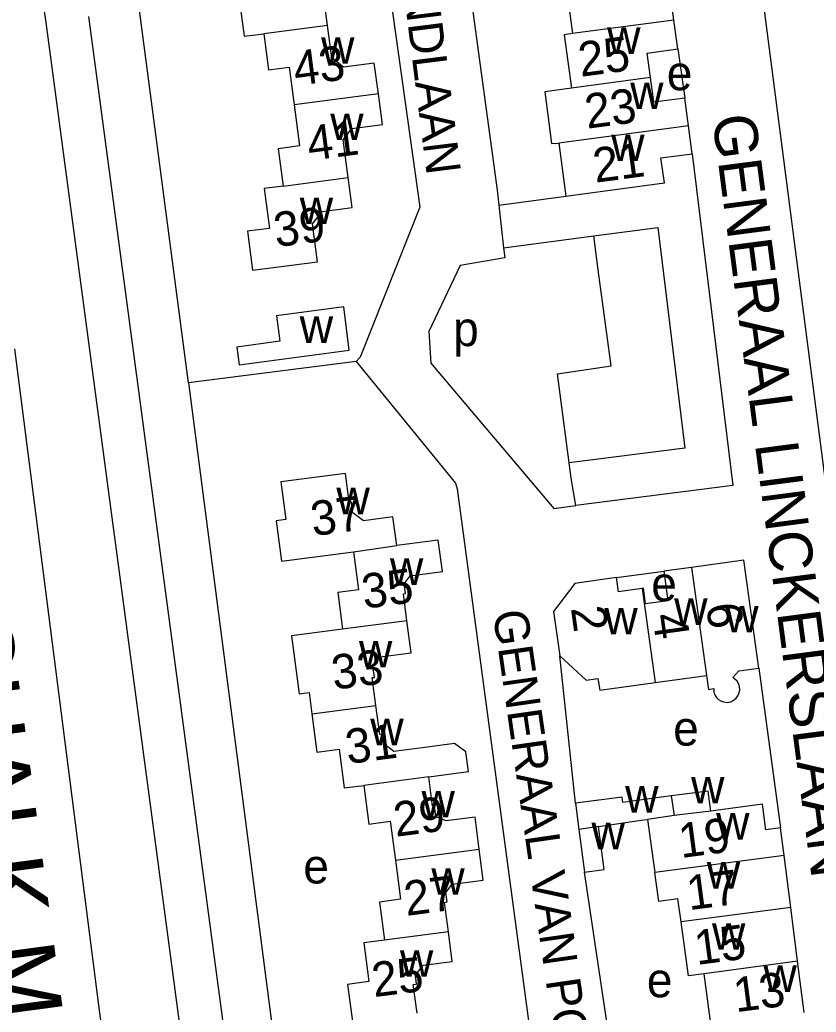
# Model space of a CAD drawing. Extents: x 159294 to 161936, y 384538 to 386517.
# Drawn here: x 161160.6 to 161252.9, y 385923.1 to 386038.1 of the extents above; entities that cross this region are included whole.
import ezdxf

# ---------------------------------------------------------------- set-up
doc = ezdxf.new("R2010")
doc.units = 0
for name, color, linetype in [('BLT_Basislijn', 7, 'Continuous'), ('BLT_Bebouwing', 7, 'Continuous'), ('BLT_Centroide', 7, 'Continuous'), ('BLT_Huisnummer', 7, 'Continuous'), ('BLT_Huisnummer_ tussenligend', 7, 'Continuous'), ('BLT_Onderverdeling_panden', 7, 'Continuous'), ('BLT_Straatnaam', 7, 'Continuous'), ('BLT_Straatnaam_hoofdweg', 7, 'Continuous'), ('BLT_Straatnaam_verkleind', 7, 'Continuous')]:
    doc.layers.add(name, color=color, linetype=linetype)

msp = doc.modelspace()

# ---------------------------------------------------------------- linework, layer by layer
at = {"layer": 'BLT_Basislijn'}
for p, q in [((161180.14, 385996.06), (161160.82, 386142.62)), ((161180.14, 385996.06), (161166.48, 386099.66)), ((161163.63, 386037.83), (161162.65, 386045)), ((161181.71, 385902.46), (161163.63, 386037.83)), ((161186.66, 385903.12), (161168.58, 386038.51)), ((161236.84, 386034.75), (161237.64, 386029.04)), ((161216.09, 386016.63), (161223.86, 386017.69)), ((161199.55, 385998.5), (161180.14, 385996.06)), ((161180.14, 385996.06), (161199.73, 385845.3)), ((161229.72, 385973.46), (161235.22, 385974.19)), ((161224.98, 385947.3), (161223.15, 385964.4)), ((161246.23, 385962.98), (161248.73, 385944.44))]:
    msp.add_line(p, q, dxfattribs=at)
for points in [[(161263.34, 386151.92), (161243.16, 386152.29), (161238.17, 386151.9), (161236, 386150.47), (161233.91, 386147.05), (161233.5, 386144.74), (161235.07, 386133.58), (161239.76, 386093.85), (161255.12, 385975.42)], [(161225.7, 386124.84), (161197.66, 386120.44), (161193.58, 386116.17), (161195.65, 386096.98), (161206.96, 386016.4), (161200.01, 385999.01), (161199.55, 385998.5)], [(161207.81, 386077.97), (161215.89, 386018.38), (161216.09, 386016.63)], [(161238.5, 386022.6), (161243.22, 385984.13), (161225.02, 385981.83)], [(161216.09, 386016.63), (161216.65, 386011.68)], [(161234.51, 386014.06), (161237.65, 385988.46), (161224.26, 385986.78)], [(161227.09, 386013.07), (161234.51, 386014.06)], [(161216.65, 386011.68), (161227.09, 386013.07)], [(161224.26, 385986.78), (161222.9, 385997.1), (161229.11, 385998.01), (161227.61, 386009.14), (161227.09, 386013.07)], [(161216.65, 386011.68), (161216.78, 386010.55), (161211.62, 386009.63), (161207.98, 386002), (161208.23, 385998.31), (161222.47, 385981.49), (161225.02, 385981.83)], [(161159.98, 386000), (161169.7, 385923.89), (161175.87, 385876.89)], [(161199.55, 385998.5), (161211.07, 385984.42), (161211.26, 385983.75), (161221.38, 385908.25), (161226.13, 385875.35), (161230.14, 385872.05), (161236.06, 385872.67)], [(161225.02, 385981.83), (161224.49, 385984.99), (161224.26, 385986.78)], [(161242.98, 385890.23), (161233.78, 385889.21), (161233.46, 385889.53), (161226.03, 385939.32)]]:
    msp.add_lwpolyline(points, dxfattribs=at)
at = {"layer": 'BLT_Bebouwing'}
for p, q in [((161236.39, 386038.09), (161235.6, 386044.03)), ((161236.84, 386034.75), (161236.39, 386038.09)), ((161238.07, 386025.82), (161237.64, 386029.04)), ((161238.5, 386022.6), (161238.07, 386025.82)), ((161238.41, 385974.64), (161235.22, 385974.19)), ((161229.95, 385971.82), (161229.72, 385973.46)), ((161234.23, 385961.3), (161240.16, 385962.13)), ((161224.98, 385947.3), (161225.38, 385944.28)), ((161225.38, 385944.28), (161226.03, 385939.32)), ((161249.15, 385941.23), (161248.73, 385944.44)), ((161249.94, 385935.24), (161249.15, 385941.23)), ((161250.71, 385928.99), (161249.94, 385935.24)), ((161251.49, 385923.05), (161250.71, 385928.99)), ((161240.65, 385921.75), (161239.89, 385927.54))]:
    msp.add_line(p, q, dxfattribs=at)
for points in [[(161182.9, 386044.87), (161183.47, 386040.49), (161185.97, 386040.82), (161186.57, 386036.22), (161188.85, 386036.51)], [(161196.23, 386037.48), (161195.75, 386041.2), (161192.26, 386040.74), (161191.01, 386041.71), (161190.47, 386045.86)], [(161223.87, 386042.34), (161224.64, 386036.52)], [(161202.14, 386029.54), (161201.67, 386033.11), (161198.1, 386032.64), (161196.73, 386033.7), (161196.23, 386037.48)], [(161188.85, 386036.51), (161189.4, 386032.34), (161191.79, 386032.65), (161192.37, 386028.27)], [(161224.64, 386036.52), (161223.68, 386036.39), (161224.5, 386030.2)], [(161233.67, 386031.42), (161233.29, 386034.27), (161236.84, 386034.75)], [(161237.64, 386029.04), (161234.05, 386028.56), (161233.67, 386031.42)], [(161224.5, 386030.2), (161221.42, 386029.78), (161222.22, 386023.77), (161223.05, 386023.82)], [(161198.64, 386019.84), (161198.07, 386024.21), (161199.08, 386025.52), (161202.6, 386025.98), (161202.14, 386029.54)], [(161192.37, 386028.27), (161192.99, 386023.5), (161190.53, 386023.18), (161191.1, 386018.85)], [(161223.05, 386023.82), (161223.2, 386022.65), (161223.86, 386017.69)], [(161226.42, 386018.03), (161235.28, 386019.21), (161234.89, 386022.12), (161238.5, 386022.6)], [(161191.1, 386018.85), (161188.91, 386018.57), (161189.51, 386013.95), (161186.96, 386013.62), (161187.55, 386009.1), (161195.07, 386010.08), (161194.49, 386014.48), (161195.61, 386015.92), (161199.09, 386016.38), (161198.64, 386019.84)], [(161223.86, 386017.69), (161226.42, 386018.03)], [(161204.27, 385977.18), (161203.83, 385980.5), (161200.4, 385980.05), (161199.19, 385980.98), (161199.03, 385982.22), (161198.77, 385982.19), (161198.34, 385985.55), (161190.85, 385984.57), (161191.42, 385980.21), (161190.31, 385980.06), (161190.92, 385975.36), (161199.27, 385976.45)], [(161205.45, 385968.45), (161205.04, 385971.6), (161205.27, 385971.62), (161205.12, 385972.76), (161205.82, 385973.68), (161209.56, 385974.16), (161209.08, 385977.81), (161204.27, 385977.18)], [(161199.27, 385976.45), (161199.84, 385972.06), (161197.43, 385971.74), (161197.99, 385967.48)], [(161244.48, 385975.49), (161238.41, 385974.64)], [(161246.23, 385962.98), (161244.48, 385975.49)], [(161229.72, 385973.46), (161224.9, 385972.79), (161222.43, 385969.53), (161223.15, 385964.4)], [(161235.22, 385974.19), (161235.69, 385970.78), (161233.11, 385970.42), (161232.85, 385972.23), (161232.7, 385972.2)], [(161232.7, 385972.2), (161229.95, 385971.82)], [(161201.86, 385958.64), (161201.43, 385961.87), (161201.68, 385961.9), (161201.51, 385963.18), (161202.34, 385964.26), (161205.93, 385964.73), (161205.45, 385968.45)], [(161197.99, 385967.48), (161192.08, 385966.71), (161192.96, 385959.98), (161194.12, 385960.13), (161194.44, 385957.67)], [(161223.15, 385964.4), (161226.21, 385961.59), (161227.59, 385961.78), (161227.79, 385960.4), (161234.23, 385961.3)], [(161240.16, 385962.13), (161240.38, 385960.51), (161241, 385960.6), (161241.02, 385960.18), (161241.14, 385959.86), (161241.34, 385959.56), (161241.55, 385959.34), (161241.83, 385959.17), (161242.15, 385959.05), (161242.65, 385959), (161243.08, 385959.12), (161243.31, 385959.25), (161243.6, 385959.48), (161243.8, 385959.74), (161243.96, 385960.09), (161244.02, 385960.46), (161244, 385960.8), (161243.87, 385961.17), (161243.71, 385961.44), (161243.45, 385961.68), (161243.23, 385961.89), (161243.92, 385962.65), (161246.23, 385962.98)], [(161207.97, 385950.36), (161212.57, 385950.97), (161212.28, 385953.26), (161210.96, 385954.22), (161207.52, 385953.77), (161203.93, 385953.3), (161202.72, 385954.24), (161202.58, 385955.33), (161202.3, 385955.29), (161201.86, 385958.64)], [(161194.44, 385957.67), (161195.02, 385953.22), (161197.6, 385953.56), (161198.18, 385949.09), (161200.45, 385949.38)], [(161200.45, 385949.38), (161201.04, 385944.89), (161203.52, 385945.22), (161204.11, 385940.7)], [(161213.83, 385941.97), (161213.34, 385945.69), (161209.99, 385945.26), (161208.81, 385945.75), (161208.64, 385946.99), (161208.41, 385946.96), (161207.97, 385950.36)], [(161236.08, 385948.15), (161230.46, 385947.41), (161230.39, 385948.01), (161224.98, 385947.3)], [(161240.67, 385946.4), (161240.37, 385948.71), (161236.08, 385948.15)], [(161248.73, 385944.44), (161247.04, 385944.22), (161246.65, 385947.19), (161240.67, 385946.4)], [(161227.64, 385944.61), (161232.59, 385945.33), (161233.34, 385945.44)], [(161233.34, 385945.44), (161234.18, 385939.26)], [(161226.03, 385939.32), (161228.3, 385939.62), (161227.64, 385944.61)], [(161210.25, 385932.4), (161209.81, 385935.82), (161210.1, 385935.86), (161209.95, 385936.95), (161210.68, 385937.91), (161214.3, 385938.38), (161213.83, 385941.97)], [(161204.11, 385940.7), (161204.7, 385936.17), (161202.26, 385935.85), (161202.84, 385931.43)], [(161237.22, 385933.57), (161236.86, 385936.22), (161234.63, 385935.92), (161234.18, 385939.26)], [(161239.89, 385927.54), (161238.07, 385927.29), (161237.22, 385933.57)], [(161206.62, 385922.98), (161206.18, 385926.3), (161206.56, 385926.35), (161206.43, 385927.38), (161207.32, 385928.54), (161210.7, 385928.98), (161210.25, 385932.4)], [(161202.84, 385931.43), (161200.46, 385931.12), (161201.05, 385926.63), (161198.57, 385926.3), (161199.14, 385922.01)]]:
    msp.add_lwpolyline(points, dxfattribs=at)
msp.add_lwpolyline([(161198.12, 386004.85), (161190.34, 386003.8), (161190.71, 386000.86), (161185.73, 386000.19), (161186.02, 385998.11), (161198.77, 385999.83)], close=True, dxfattribs=at)
at = {"layer": 'BLT_Onderverdeling_panden'}
for p, q in [((161236.39, 386038.09), (161224.64, 386036.52)), ((161196.23, 386037.48), (161188.85, 386036.51)), ((161233.67, 386031.42), (161224.5, 386030.2)), ((161202.14, 386029.54), (161192.37, 386028.27)), ((161238.07, 386025.82), (161223.05, 386023.82)), ((161191.1, 386018.85), (161198.64, 386019.84)), ((161199.27, 385976.45), (161204.27, 385977.18)), ((161238.41, 385974.64), (161240.16, 385962.13)), ((161232.7, 385972.2), (161234.23, 385961.3)), ((161205.45, 385968.45), (161197.99, 385967.48)), ((161194.44, 385957.67), (161201.86, 385958.64)), ((161207.97, 385950.36), (161200.45, 385949.38)), ((161236.08, 385948.15), (161236.4, 385945.87)), ((161236.4, 385945.87), (161233.34, 385945.44)), ((161240.67, 385946.4), (161236.4, 385945.87)), ((161227.64, 385944.61), (161225.38, 385944.28)), ((161204.11, 385940.7), (161213.83, 385941.97)), ((161249.15, 385941.23), (161234.18, 385939.26)), ((161249.94, 385935.24), (161237.22, 385933.57)), ((161210.25, 385932.4), (161202.84, 385931.43)), ((161250.71, 385928.99), (161239.89, 385927.54))]:
    msp.add_line(p, q, dxfattribs=at)

# ---------------------------------------------------------------- texts
at = {"layer": 'BLT_Centroide'}
for s, p in [('w', (161228.65, 386034.16)), ('w', (161195.5, 386033.03)), ('e', (161235.56, 386029.96)), ('w', (161231.32, 386027.78)), ('w', (161196.56, 386024.19)), ('w', (161229.12, 386021.75)), ('w', (161193.03, 386014.45)), ('w', (161193.03, 386000.66)), ('p', (161210.8, 386000.3)), ('w', (161197.28, 385980.8)), ('w', (161203.48, 385972.62)), ('e', (161233.76, 385970.74)), ('w', (161228.33, 385966.88)), ('w', (161236.42, 385967.98)), ('w', (161242.33, 385967.11)), ('w', (161199.89, 385963.05)), ('w', (161201.2, 385954.02)), ('e', (161236.3, 385953.99)), ('w', (161230.74, 385946.22)), ('w', (161238.38, 385947.28)), ('w', (161207.14, 385945.67)), ('w', (161241.28, 385943.09)), ('w', (161226.84, 385941.97)), ('e', (161193.44, 385938.01)), ('w', (161240.2, 385937.41)), ('w', (161208.28, 385936.7)), ('w', (161240.8, 385930.32)), ('w', (161204.64, 385927.19)), ('e', (161233.25, 385924.82)), ('w', (161246.76, 385925.44))]:
    msp.add_text(s, height=4, dxfattribs=at).set_placement(p)
at = {"layer": 'BLT_Huisnummer'}
for s, rotation, p in [('25', 7.5901, (161225.58, 386031.51)), ('43', 7.4418, (161192.55, 386030.46)), ('21', 7.5901, (161227.28, 386019.23)), ('39', 7.4418, (161190.28, 386011.76)), ('37', 7.4616, (161194.56, 385978.26)), ('2', 277.9407, (161224.44, 385969.93)), ('6', 277.9407, (161240.1, 385970.29)), ('33', 7.4616, (161196.98, 385960.45)), ('29', 7.4616, (161204.15, 385943.41)), ('19', 7.5091, (161237.21, 385940.95)), ('25', 7.4616, (161201.64, 385924.82)), ('13', 7.5091, (161243.56, 385923.07))]:
    msp.add_text(s, height=4, rotation=rotation, dxfattribs=at).set_placement(p)
at = {"layer": 'BLT_Huisnummer_ tussenligend'}
for s, rotation, p in [('23', 7.5901, (161226.33, 386025.49)), ('41', 7.4418, (161194.15, 386021.78)), ('35', 7.4616, (161200.48, 385969.84)), ('4', 277.9407, (161233.88, 385969.09)), ('31', 7.4616, (161198.59, 385951.84)), ('27', 7.4616, (161205.38, 385934.24)), ('17', 7.5091, (161238.14, 385934.9)), ('15', 7.5091, (161239.03, 385928.55))]:
    msp.add_text(s, height=4, rotation=rotation, dxfattribs=at).set_placement(p)
at = {"layer": 'BLT_Straatnaam'}
msp.add_text('GENERAAL LINCKERSLAAN', height=5, rotation=277.4489, dxfattribs=at).set_placement((161240.81, 386026.89))
at = {"layer": 'BLT_Straatnaam_hoofdweg'}
msp.add_text('VELDMAARSCHALK MONTGOMERYLAAN', height=7.9999, rotation=277.6475, dxfattribs=at).set_placement((161142.6, 386034.38))
at = {"layer": 'BLT_Straatnaam_verkleind'}
for rotation, p in [(277.1684, (161197, 386105.52)), (278.1684, (161215.39, 385969.47))]:
    msp.add_text('GENERAAL VAN PORTLANDLAAN', height=4, rotation=rotation, dxfattribs=at).set_placement(p)

doc.saveas('drawing.dxf')
